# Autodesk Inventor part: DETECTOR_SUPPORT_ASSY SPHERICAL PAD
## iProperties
Shininess: 64.0
Length Units: 11272
Angle Units: 11279
Time Units: 11290
Mass Units: 11286
Length Display Precision: 3
Angle Display Precision: 2
Compacted: True
Part Number: DETECTOR_SUPPORT_ASSY SPHERICAL PAD
Document SubType Name: Modeling
Created: 2004-08
Designer: John Blackburn
Material: STAINLESS_STEEL, AUSTENITIC
Manufacturer: Standard
Standards Organization: Custom
Density: 0.0
Volumn: 0.0
Area: 0.0
PropertySet Name: Model Information
Control State: 0
Master: False
Checked Out: False
Author: John Blackburn
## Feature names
1. ExtrusionBlind1
2. RevolutionAngle1
3. Hole1
4. Rectangular Pattern1
